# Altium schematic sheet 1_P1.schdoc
size 431 x 309 mm; Symbol: Sheet-Symbol_A3; Device: Sheet-Symbol_A3; Company: 嘉立创EDA; Version: V1.0; Page Size: A3; @Project Name: 辉光管_2024.2.16; @Page Count: 1; @Update Date: 2024-07-20; @Create Date: 2024-07-11; @Schematic Name: Schematic7; @Page No: 1; @Page Name: P1
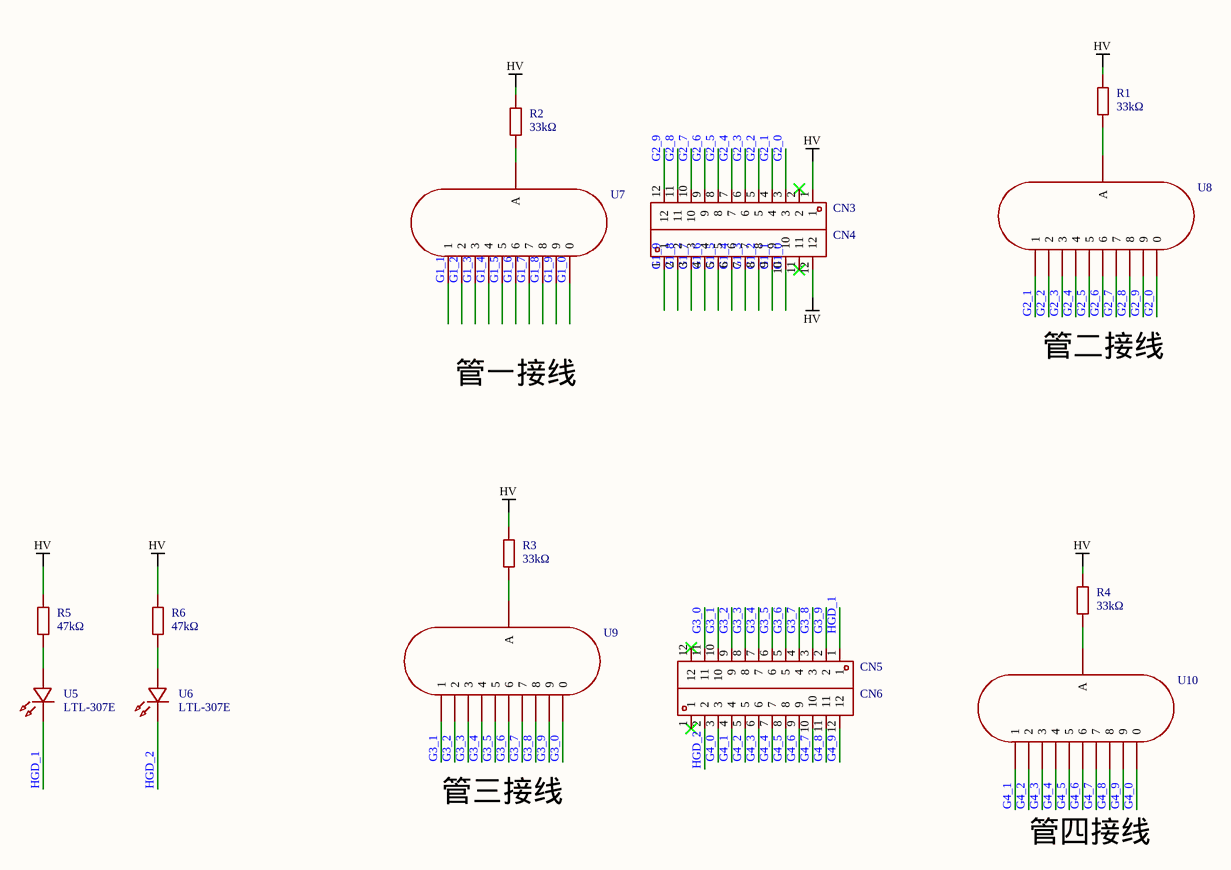
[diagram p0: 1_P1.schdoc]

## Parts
CN3  HB-PH3-254112PB2GOP  [HDR-TH_12P-P2.54-V-M]  (value not drawn)
CN4  HB-PH3-254112PB2GOP  [HDR-TH_12P-P2.54-V-M]  (value not drawn)
CN5  HB-PH3-254112PB2GOP  [HDR-TH_12P-P2.54-V-M]  (value not drawn)
CN6  HB-PH3-254112PB2GOP  [HDR-TH_12P-P2.54-V-M]  (value not drawn)
R1  33kΩ  [R0805]  (value not drawn)
R2  33kΩ  [R0805]  (value not drawn)
R3  33kΩ  [R0805]  (value not drawn)
R4  33kΩ  [R0805]  (value not drawn)
R5  47kΩ  [R0805]  (value not drawn)
R6  47kΩ  [R0805]  (value not drawn)
U5  LTL-307E  [LED-TH_BD5.9-P2.54-RD_RED]  (value not drawn)
U6  LTL-307E  [LED-TH_BD5.9-P2.54-RD_RED]  (value not drawn)
U7  IN-12A_  [IN-12]  (value not drawn)
U8  IN-12A_  [IN-12]  (value not drawn)
U9  IN-12A_  [IN-12]  (value not drawn)
U10  IN-12A_  [IN-12]  (value not drawn)

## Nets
HV: CN3.1 CN4.12 R1.2 R2.2 R3.2 R4.2 R5.2 R6.2
G1_0: CN4.10 U7.0
G1_1: CN4.9 U7.1
G1_2: CN4.8 U7.2
G1_3: CN4.7 U7.3
G1_4: CN4.6 U7.4
G1_5: CN4.5 U7.5
G1_6: CN4.4 U7.6
G1_7: CN4.3 U7.7
G1_8: CN4.2 U7.8
G1_9: CN4.1 U7.9
G2_0: CN3.3 U8.0
G2_1: CN3.4 U8.1
G2_2: CN3.5 U8.2
G2_3: CN3.6 U8.3
G2_4: CN3.7 U8.4
G2_5: CN3.8 U8.5
G2_6: CN3.9 U8.6
G2_7: CN3.10 U8.7
G2_8: CN3.11 U8.8
G2_9: CN3.12 U8.9
G3_0: CN5.11 U9.0
G3_1: CN5.10 U9.1
G3_2: CN5.9 U9.2
G3_3: CN5.8 U9.3
G3_4: CN5.7 U9.4
G3_5: CN5.6 U9.5
G3_6: CN5.5 U9.6
G3_7: CN5.4 U9.7
G3_8: CN5.3 U9.8
G3_9: CN5.2 U9.9
G4_0: CN6.3 U10.0
G4_1: CN6.4 U10.1
G4_2: CN6.5 U10.2
G4_3: CN6.6 U10.3
G4_4: CN6.7 U10.4
G4_5: CN6.8 U10.5
G4_6: CN6.9 U10.6
G4_7: CN6.10 U10.7
G4_8: CN6.11 U10.8
G4_9: CN6.12 U10.9
HGD_1: CN5.1 U5.1(C)
HGD_2: CN6.2 U6.1(C)
NetR1_1: R1.1 U8.A
NetR2_1: R2.1 U7.A
NetR3_1: R3.1 U9.A
NetR4_1: R4.1 U10.A
NetR5_1: R5.1 U5.2(A)
NetR6_1: R6.1 U6.2(A)

Not connected (* = marked no-connect by the designer): CN3 2*; CN4 11*; CN5 12*; CN6 1*

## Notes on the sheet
- 管二接线
- 管一接线
- 管三接线
- 管四接线

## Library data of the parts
CN3-CN6 = HB-PH3-254112PB2GOP: 插针结构:1x12P;间距:2.54mm;行距:2.54mm;圆针/方针:方针;安装类型:直插;排数:单排;总PIN位数:12P;额定电流:3A;额定电压:250V;配合针长度:6mm;塑高:2.54mm;端接针长度:3mm;触头材质:黄铜;触头镀层:金;工作温度范围:-40℃~+105℃;焊接温度(最大值):260℃;颜色:黑色;; Manufacturer: HANBO(汉博); Add into BOM: yes; Pin Structure: 1x12P; Pitch: 2.54mm; Circluar Pins/Square Pins: 方针; Current Rating (Max): 3A; Voltage Rating (Max): 250V; Soldering Temperature(Max): 260℃
R1-R4 = 0805W8F3302T5E: 电阻类型:厚膜电阻;阻值:33kΩ;精度:±1%;功率:125mW;最大工作电压:150V;温度系数:±100ppm/℃;; Manufacturer: UNI-ROYAL(厚声); Add into BOM: yes; Tolerance: ±1%; Power(Watts): 125mW; Overload Voltage (Max): 150V
R5 R6 = 0805W8F4702T5E: 电阻类型:厚膜电阻;阻值:47kΩ;精度:±1%;功率:125mW;最大工作电压:150V;温度系数:±100ppm/℃;; Manufacturer: UNI-ROYAL(厚声); Add into BOM: yes; Tolerance: ±1%; Power(Watts): 125mW; Overload Voltage (Max): 150V
U5 U6 = LTL-307E: 发光颜色:红色;正向电压(VF):2V;正向电流:20mA;主波长:623nm;透镜颜色:红色透镜;发光强度:19mcd;发光角度:50°;; Manufacturer: LITEON(光宝); Add into BOM: yes; Emitted Color: 红色; Forward Voltage (VF): 2V; Forward Current: 20mA; Dominant Wavelength: 623nm; Peak Wavelength: 635nm; Lens Color: 红色透镜; Luminous Intensity: 19mcd; Viewing Angle: 50°
U7-U10 = IN-12A_: Add into BOM: yes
